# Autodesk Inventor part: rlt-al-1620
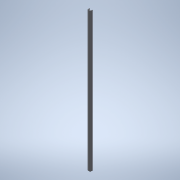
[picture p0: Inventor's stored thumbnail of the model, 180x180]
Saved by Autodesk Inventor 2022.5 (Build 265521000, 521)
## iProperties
Created: 2016-12
Part Number: rlt-al-1620
Material: 一般
Document SubType Name: Modeling
Designer: imaocorp
Density: 1 g/cm^3
Appearance: 既定
Author: imaocorp
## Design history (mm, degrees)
node "rlt-al-1620.x_t1"
node "rlt-al-1620"
node "Base1"
